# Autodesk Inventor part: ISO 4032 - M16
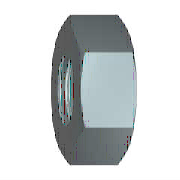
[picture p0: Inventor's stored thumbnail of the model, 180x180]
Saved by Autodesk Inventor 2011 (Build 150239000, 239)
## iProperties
IsCustomPart: 0
Created: 2009-02
Part Number: ISO 4032 - M16
Material: Stainless Steel, 440C
Description: Hexagon nuts, style 1 - Product grades A and B
Document SubType Name: Modeling
Standard: ISO 4032
Designer: V.de Jong
Standard Revision: Third edition 1999-08-15
Standards Organization: ISO
Language: en-US
Size Designation: M16
Categories: <MemberInstance><Categories><Category DisplayName="Fasteners" InternalName="e4da775c-781d-43d5-af7c-5136215cf5a6" Mnemonic="FSTN"><Category DisplayName="Nuts" I
Density: 7.75 g/cm^3
Mass: 39.003 g
Surface Area: 24.3034 cm^2
Volume: 5.03264 cm^3
Author: V.de Jong
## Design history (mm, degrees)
body "Solid1"
workaxis "Work Axis1"
workplane "Work Plane1"
sketch "Sketch1"
  geometry: L1 (-13.856, 0)-(-6.928, 12); L2 (-6.928, 12)-(6.928, 12); L3 (6.928, 12)-(13.856, 0); L4 (13.856, 0)-(6.928, -12); L5 (6.928, -12)-(-6.928, -12); L6 (-6.928, -12)-(-13.856, 0); 2 further points
  constraints: 12 end point, 1 coincident, 1 horizontal, 11 other
  dimensions: "d0" = 27.71281 distance of L3.end L1.start (= 1.1547 x SW)
extrude "Body" new body sketch "Sketch1" distance "d1" = 14.8 (= KOH); taper "d2" = 0 deg
revolve "Chamfer1" stored, may be unused: angle "d7" = 90 deg
sketch "Sketch3"
  geometry: 4 further points
  constraints: 1 coincident, 1 other
hole "Thread" sketch "Sketch3" diameter "d25" = 13.835; stored, may be unused: countersink angle "d29" = 82 deg, drill point angle "d31" = 118 deg; dims "d26" = 6, "d27" = 4, "d28" = 2, "d30" = 8
chamfer "Chamfer2" distance "d8" = 1.08253 (= -0.5 x GD1 + 0.5 x NND); stored, may be unused: angle "d9" = 30 deg, second distance "d40" = 1.08253 (= -0.5 x GD1 + 0.5 x NND)
chamfer "Chamfer3" distance "d10" = 1.08253 (= -0.5 x GD1 + 0.5 x NND); stored, may be unused: angle "d11" = 30 deg, second distance "d41" = 1.08253 (= -0.5 x GD1 + 0.5 x NND)
sketch "Sketch2"
  geometry: L1 (0, 6.928)-(0, 13.856) reference; L2 (0, 13.856)-(14.8, 13.856) reference; L3 (14.8, 6.928)-(14.8, 13.856) reference; L4 (-2.96, 0)-(17.76, 0) reference; L5 (1.505, 13.856)-(0, 11.25); L6 (13.295, 13.856)-(14.8, 11.25)
  constraints: 4 end point, 4 point on line
  dimensions: "d3" = 30 deg angle of L1 L5 (= ANG1); "d4" = 30 deg angle of L3 L6 (= ANG2); "d5" = 22.5 diameter of L5.end L4 (= SW0); "d6" = 22.5 diameter of L6.end L4 (= SW01)
other parameters: "ANG1" = 30 deg [user parameter; used in 1 equation term], "ANG2" = 30 deg [user parameter; used in 1 equation term], "NND" = 16 [user parameter; used in 4 equation terms], "KOH" = 14.8 [user parameter; used in 1 equation term], "SW" = 24 [user parameter; used in 2 equation terms], "SW0" = 22.5 [user parameter; used in 2 equation terms], "SW01" = 22.5 (= SW0) [user parameter; used in 1 equation term], "GD1" = 13.83494 (computed from THREADDIA, PTC, TOA) [user parameter; used in 4 equation terms], "d13" = 0, "d14" = 0, "d39" = 0, "d42" = 0, "GUL" = 1.08253 (= 0.541266 x PTC) [user parameter], "TPU" = 5 (computed from PTC) [user parameter], "THREADDIA" = 16 [user parameter; used in 1 equation term], "TOA" = 30 deg [user parameter; used in 1 equation term], "PTC" = 2 [user parameter; used in 4 equation terms], "E0" = 27.72 (= 1.155 x SW) [user parameter], "GAL" = 1.08253 (= 0.541266 x PTC) [user parameter]
